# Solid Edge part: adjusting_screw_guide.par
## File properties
Title: Adjusting screw guide
Author: Robert a Rhodes jr
Template: Normal.par
Last saved by: CADCIM
Revision: 6
Application: Solid Edge
Density: 0 kg/mm^3
Accuracy: 0.99
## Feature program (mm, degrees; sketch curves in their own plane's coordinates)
sketch for "unnamed Protrusion 1" plane through (0, 0, 0) normal (0, -1, 0) x-axis (1, 0, 0)
  circle centre (0, 0) radius 12.7
extrude "unnamed Protrusion 1" add finite 63.5 along +normal
sketch for "ExtrudedProtrusion_2" plane through (0, -63.5, 0) normal (0, -1, 0) x-axis (1, 0, 0)
  circle centre (0, 0) radius 9.525
extrude "ExtrudedProtrusion_2" add finite 76.2 along +normal
chamfer "Chamfer_1" setback 1.5748
sketch for "ExtrudedCutout_1" plane through (0, 0, 0) normal (0, 0, 1) x-axis (1, 0, 0)
  line (1.1811, 0) -> (1.1811, -9.398)
  line (1.1811, -9.398) -> (-1.1811, -9.398)
  line (-1.1811, -9.398) -> (-1.1811, 0)
  line (-1.1811, 0) -> (1.1811, 0)
extrude "ExtrudedCutout_1" cut finite 101.6 symmetric
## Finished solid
Body 1: solid body, 10 faces, 16 edges, 8 vertices.
  Faces by surface: plane 7, cylinder 2, cone 1
  Edges by curve: circle 8, line 8
Bounding box of the edges (mm): 25.400 x 139.700 x 25.400, from (-12.7, -139.7, -12.7) to (12.7, 0, 12.7).
Cylindrical faces by radius (mm): R9.525 x1, R12.7 x1
Conical faces (half-angle, radius in mm at the cone's reference point): 45 deg R9.525 x1
Planar faces by outward normal: +x 1, +y 3, -x 1, -y 2
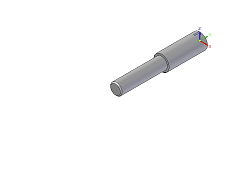
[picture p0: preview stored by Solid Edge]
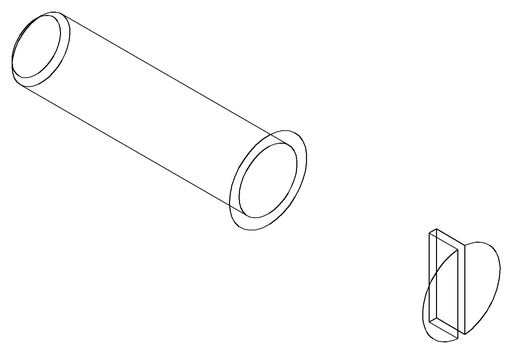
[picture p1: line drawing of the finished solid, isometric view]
